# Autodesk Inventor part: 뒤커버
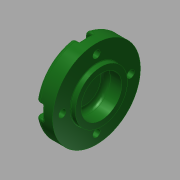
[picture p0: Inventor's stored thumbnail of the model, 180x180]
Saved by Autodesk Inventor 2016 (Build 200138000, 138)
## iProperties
Created: 2015-11
Part Number: 뒤커버
Material: 알루미늄 6061
Document SubType Name: Modeling
Designer: mduedu
Density: 1 g/cm^3
Appearance: 매끄러움 - 짙은 산림 녹색
Author: mduedu
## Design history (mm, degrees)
sketch "스케치1"
  geometry: L1 (-7, 0)-(7, 0); L2 (-7, 0)-(-7, 27); L3 (-7, 27)-(4, 27); L4 (4, 27)-(4, 16); L5 (4, 16)-(7, 16); L6 (7, 16)-(7, 0); 2 further points
  constraints: 12 end point, 3 perpendicular, 2 parallel, 1 coincident, 1 horizontal, 1 midpoint
  dimensions: "d0" = 14 distance of L1.start L1.end; "d1" = 54 diameter of L3 L1; "d2" = 3 distance of L4.end L5.end; "d3" = 32 diameter of L5 L1
revolve "회전1" sketch "스케치1" stored, may be unused: angle "d4" = 90 deg
hole "구멍1" diameter "d7" = 25; stored, may be unused: countersink angle "d11" = 90 deg, drill point angle "d13" = 0 deg; dims "d8" = 6, "d9" = 4, "d10" = 2, "d12" = 10, "d66" = 10, "d67" = 10
fillet "모깎기2" dims "d36" = 3
fillet "모깎기3" dims "d37" = 3
fillet "모깎기4" dims "d38" = 0.3
sketch "스케치3" dims "d61" = 42
  geometry: C1 r 27 at (0, 0) reference; 2 further points
  constraints: 2 vertical alignment, 1 coincident, 2 other
hole "구멍4" sketch "스케치3" at (0, 21) diameter "d44" = 4.5; stored, may be unused: countersink angle "d48" = 90 deg, drill point angle "d50" = 0 deg; dims "d45" = 6, "d46" = 8, "d47" = 4.6, "d49" = 8
sketch "스케치4"
  geometry: L1 (-4, 5.702)-(-4, 0); L2 (4, 5.702)-(4, 0); A1 r 27 centre (0, -21) between (-4, 5.702) and (4, 5.702) reference; A2 r 4 centre (0, 0) between (-2.824, 2.833) and (2.824, 2.833) reference
  constraints: 4 end point, 4 point on circle, 2 tangent, 2 vertical
extrude "돌출1" cut sketch "스케치4" stored distance "d51" = 0; taper "d52" = 0 deg
fillet "모깎기5" dims "d56" = 0.3
fillet "모깎기6" dims "d57" = 1
node "솔리드1"
pattern_circular "원형 패턴2" dims angle "d64" = 360 deg
pattern_circular "원형 패턴1" dims angle "d54" = 360 deg
